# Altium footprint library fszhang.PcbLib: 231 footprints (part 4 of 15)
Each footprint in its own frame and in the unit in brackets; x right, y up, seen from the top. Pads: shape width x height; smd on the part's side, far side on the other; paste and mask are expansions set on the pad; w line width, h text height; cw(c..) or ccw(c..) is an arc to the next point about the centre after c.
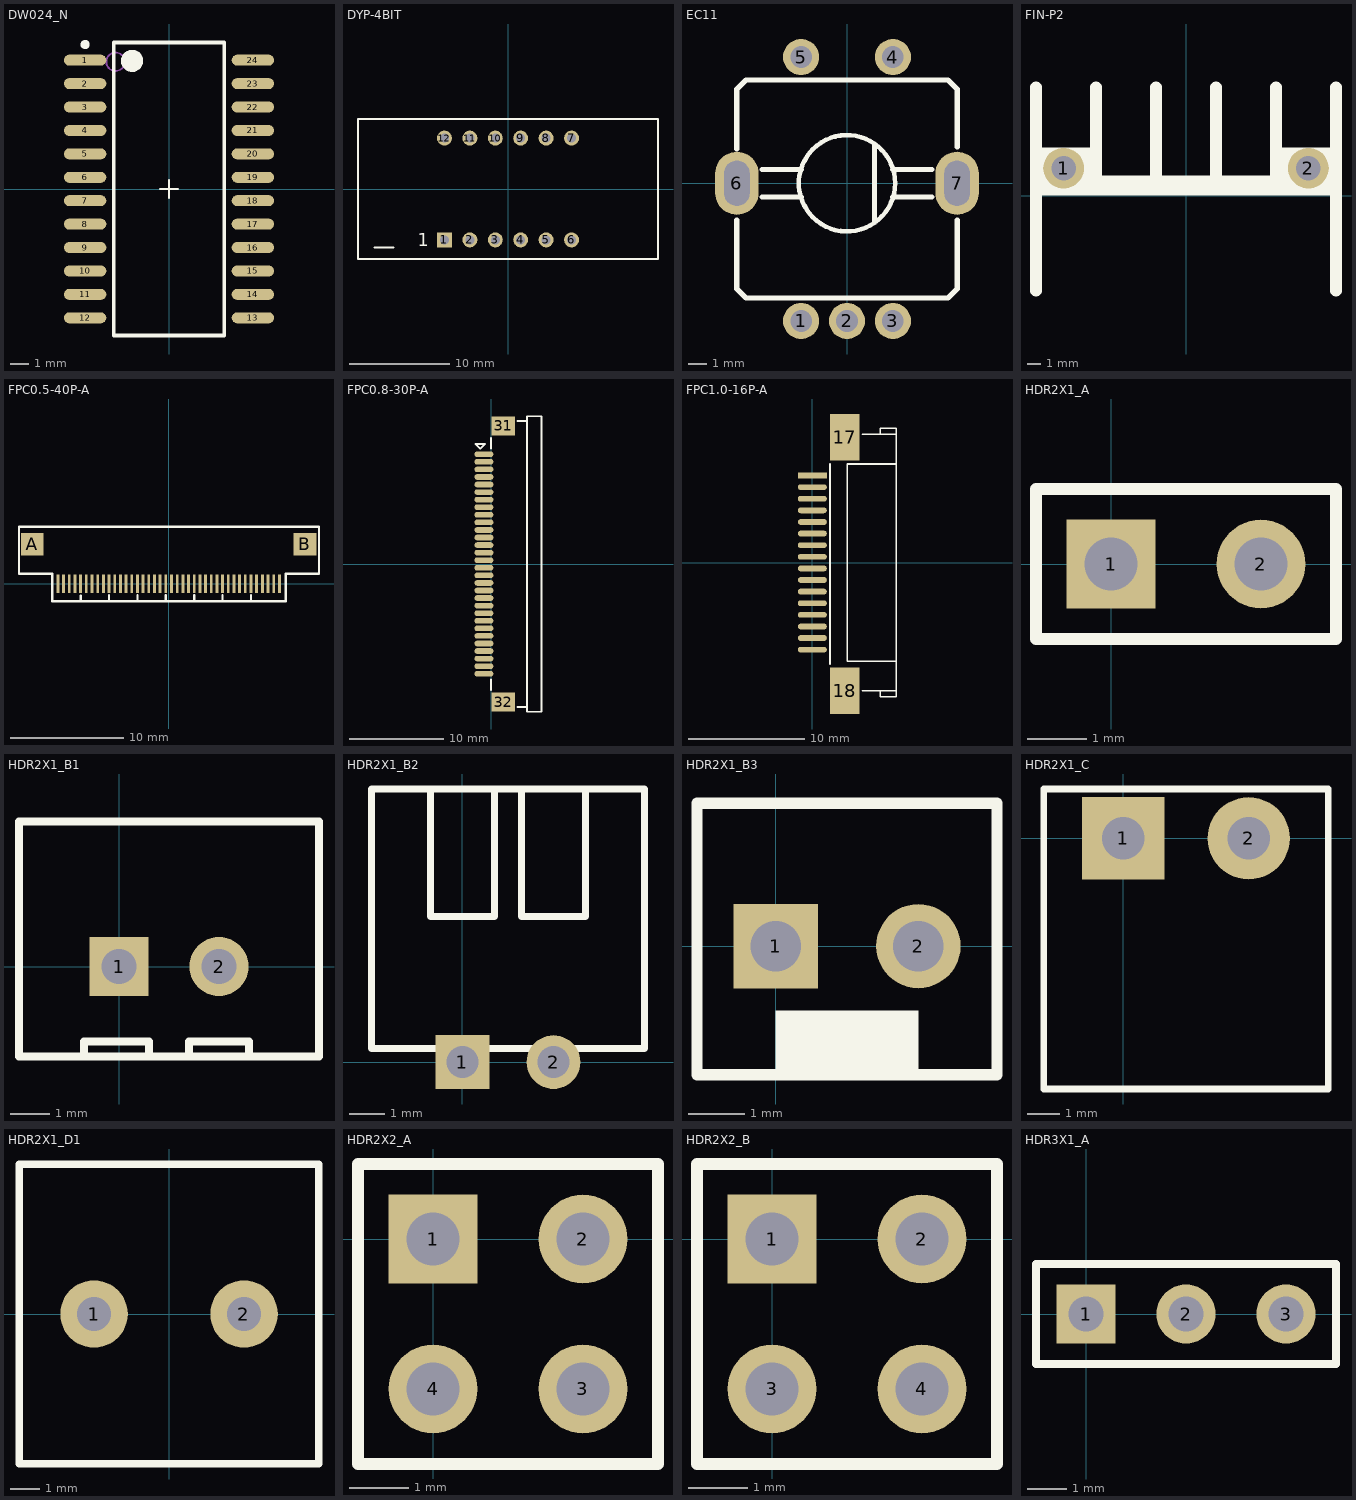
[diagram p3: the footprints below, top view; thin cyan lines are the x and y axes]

## DW024_N [mm] "74hc154"
height 2.65
pads (24):
  oval 2.3x0.6 smd: 1(-4.55,6.985) 2(-4.55,5.715) 3(-4.55,4.445) 4(-4.55,3.175) 5(-4.55,1.905) 6(-4.55,0.635) 7(-4.55,-0.635) 8(-4.55,-1.905) 9(-4.55,-3.175) 10(-4.55,-4.445) 11(-4.55,-5.715) 12(-4.55,-6.985) 13(4.55,-6.985) 14(4.55,-5.715) 15(4.55,-4.445) 16(4.55,-3.175) 17(4.55,-1.905) 18(4.55,-0.635) 19(4.55,0.635) 20(4.55,1.905) 21(4.55,3.175) 22(4.55,4.445) 23(4.55,5.715) 24(4.55,6.985)
Top Overlay:
  circle w0.25: c-4.55,7.835 r0.125
  circle w0.6: c-2,6.95 r0.3
  lines w0.1: -0.5,0 0.5,0 ; 0,-0.5 0,0.5
  lines w0.2: -3,-7.95 -3,7.95 3,7.95 3,-7.95 -3,-7.95
Mechanical 13:
  circle w0.1: c-2.9,6.9 r0.5
3D body: height 2.65, standoff 0, extent -3.8,-7.8 3.8,7.8

## DYP-4BIT [mm] "数码管"
height 1.2
pads (12):
  rect 1.5x1.5 hole 0.9: 1(-6.35,-5.08)
  round 1.5 hole 0.9: 2(-3.81,-5.08) 3(-1.27,-5.08) 4(1.27,-5.08) 5(3.81,-5.08) 6(6.35,-5.08) 7(6.35,5.08) 8(3.81,5.08) 9(1.27,5.08) 10(-1.27,5.08) 11(-3.81,5.08) 12(-6.35,5.08)
Top Overlay:
  lines w0.2: -13.335,-5.842 -11.43,-5.842 ; -14.986,-6.985 14.986,-6.985 14.986,6.985 -14.986,6.985 -14.986,-6.985
  text "1" at -9.017,-5.715 h1.27

## EC11 [mm]
pads (7):
  round 2 hole 1.2: 1(-2.54,-7.62) 2(0,-7.62) 3(2.54,-7.62) 4(2.54,6.985) 5(-2.54,6.985)
  oval 2.4x3.5 hole 1.4 slot 2.5 at 90 deg: 6(-6.096,0) 7(6.096,0)
Top Overlay:
  circle w0.254: c0,0 r2.667
  lines w0.3: -6.096,-2.032 -6.096,-5.842 -5.588,-6.35 5.588,-6.35 6.096,-5.842 6.096,-2.032 ; -6.096,1.905 -6.096,5.207 -5.588,5.715 5.588,5.715 6.096,5.207 6.096,2.032 ; -4.699,-0.762 -2.54,-0.762 ; -4.699,0.762 -2.54,0.762 ; 1.524,-2.159 1.524,2.159 ; 2.54,-0.762 4.699,-0.762 ; 2.54,0.762 4.699,0.762

## FIN-P2 [mm] "散热片"
height 1.9
pads (2):
  round 3 hole 1.8: 1(-9.017,2.032) 2(9.017,2.032)
Top Overlay:
  rectangle: 6.629,1.27 11.049,3.556
  rectangle: -11.049,0.889 -6.629,3.556
  lines w0.85: -11.049,-7 -11.049,8 ; -6.629,0.762 -6.629,8.001 ; -2.21,0.762 -2.21,8.001 ; 2.21,0.762 2.21,8.001 ; 6.629,0.762 6.629,8.001 ; 11.049,-7 11.049,8
  lines w1.5: -10.668,0.762 10.668,0.762

## FPC0.5-40P-A [mm]
height 1
pads (42):
  rect 0.25x1.6 smd: 1(-9.78,0.011) 2(-9.28,0.011) 3(-8.78,0.011) 4(-8.28,0.011) 5(-7.78,0.011) 6(-7.28,0.011) 7(-6.78,0.011) 8(-6.28,0.011) 9(-5.78,0.011) 10(-5.28,0.011) 11(-4.78,0.011) 12(-4.28,0.011) 13(-3.78,0.011) 14(-3.28,0.011) 15(-2.78,0.011) 16(-2.28,0.011) 17(-1.78,0.011) 18(-1.28,0.011) 19(-0.78,0.011) 20(-0.28,0.011) 21(0.22,0.011) 22(0.72,0.011) 23(1.22,0.011) 24(1.72,0.011) 25(2.22,0.011) 26(2.72,0.011) 27(3.22,0.011) 28(3.72,0.011) 29(4.22,0.011) 30(4.72,0.011) 31(5.22,0.011) 32(5.72,0.011) 33(6.22,0.011) 34(6.72,0.011) 35(7.22,0.011) 36(7.72,0.011) 37(8.22,0.011) 38(8.72,0.011) 39(9.22,0.011) 40(9.72,0.011)
  rect 2x2 smd: A(-12.029,3.5) B(11.971,3.5)
Top Overlay:
  lines w0.2: -10.287,-1.524 -10.287,0.889 -13.208,0.889 -13.208,5.036 13.208,5.036 13.208,1.27 13.208,0.889 10.287,0.889 10.287,-1.514 -10.287,-1.514 ; -7.78,-1.514 -7.78,-1.014 ; -5.28,-1.514 -5.28,-0.989 ; -2.78,-1.489 -2.78,-0.989 ; -0.28,-1.464 -0.28,-0.964 ; 2.22,-1.464 2.22,-0.964 ; 4.72,-1.464 4.72,-0.964 ; 7.22,-1.464 7.22,-0.964

## FPC0.8-30P-A [mm] "FPC"
height 1.2
pads (32):
  oval 2x0.6 smd: 1(-0.762,11.6) 2(-0.762,10.8) 3(-0.762,10) 4(-0.762,9.2) 5(-0.762,8.4) 6(-0.762,7.6) 7(-0.762,6.8) 8(-0.762,6) 9(-0.762,5.2) 10(-0.762,4.4) 11(-0.762,3.6) 12(-0.762,2.8) 13(-0.762,2) 14(-0.762,1.2) 15(-0.762,0.4) 16(-0.762,-0.4) 17(-0.762,-1.2) 18(-0.762,-2) 19(-0.762,-2.8) 20(-0.762,-3.6) 21(-0.762,-4.4) 22(-0.762,-5.2) 23(-0.762,-6) 24(-0.762,-6.8) 25(-0.762,-7.6) 26(-0.762,-8.4) 27(-0.762,-9.2) 28(-0.762,-10) 29(-0.762,-10.8) 30(-0.762,-11.6)
  rect 2.5x2 smd: 31(1.27,14.605) 32(1.27,-14.605)
Top Overlay:
  lines w0.2: 0,-13.335 0,-12.192 ; 0,12.192 0,13.335 ; 2.794,-15.113 3.81,-15.113 ; 2.794,15.113 3.81,15.113 ; 3.81,-15.113 3.81,-15.621 5.334,-15.621 5.334,15.621 3.81,15.621 3.81,15.113 ; 3.81,-15.113 3.81,15.113 ; -1.651,12.7 -1.524,12.7 -0.635,12.7 -1.143,12.192 -1.651,12.7

## FPC1.0-16P-A [mm] "FPC"
height 1.2
pads (18):
  rect 2.5x0.5 smd: 1(0,7.493)
  oval 2.5x0.5 smd: 2(0,6.493) 3(0,5.493) 4(0,4.493) 5(0,3.493) 6(0,2.493) 7(0,1.493) 8(0,0.493) 9(0,-0.507) 10(0,-1.507) 11(0,-2.507) 12(0,-3.507) 13(0,-4.507) 14(0,-5.507) 15(0,-6.507) 16(0,-7.507)
  rect 2.5x4 smd: 17(2.794,10.795) 18(2.794,-11.049)
Top Overlay:
  lines w0.15: 1.524,-8.763 1.524,8.509 ; 4.318,-11.049 7.224,-11.049 ; 4.318,11.049 7.224,11.049 ; 5.842,11.049 5.842,11.557 7.224,11.557 7.224,11.049 ; 6.096,-11.049 5.842,-11.049 5.842,-11.557 7.224,-11.557 7.224,-11.049 ; 7.224,-8.507 3,-8.507 3,8.493 7.224,8.493 ; 7.224,-11.049 7.224,11.049

## HDR2X1_A [mm] "Connector; Header; 2 Position"
height 7.01
pads (2):
  rect 1.5x1.5 hole 0.9: 1(0,0)
  round 1.5 hole 0.9: 2(2.54,0)
Top Overlay:
  lines w0.2: -1.27,-1.27 3.81,-1.27 3.81,1.27 -1.27,1.27 -1.27,-1.27

## HDR2X1_B1 [mm] "Connector; Header; 4 Position"
height 1.6
pads (2):
  rect 1.5x1.5 hole 0.9: 1(0,0)
  round 1.5 hole 0.9: 2(2.54,0)
Top Overlay:
  lines w0.2: -0.889,-2.286 -0.889,-1.905 0.762,-1.905 0.762,-2.286 ; 1.778,-2.286 1.778,-1.905 3.302,-1.905 3.302,-2.286 ; -2.54,-2.286 5.08,-2.286 5.08,3.683 -2.54,3.683 -2.54,-2.286
3D body: height 1.5, standoff 0, extent -2.413,-2.159 5.08,3.556

## HDR2X1_B2 [mm] "Connector; Header; 4 Position"
height 1.6
pads (2):
  rect 1.5x1.5 hole 0.9: 1(0,0)
  round 1.5 hole 0.9: 2(2.54,0)
Top Overlay:
  lines w0.2: -0.889,7.62 -0.889,4.064 0.889,4.064 0.889,7.62 ; 1.651,7.62 1.651,4.064 3.429,4.064 3.429,7.62 ; -2.54,0.381 5.08,0.381 5.08,7.62 -2.54,7.62 -2.54,0.381
3D body: height 1.5, standoff 0, extent -2.54,0.381 5.08,7.62

## HDR2X1_B3 [mm] "Connector; Header; 4 Position"
height 1.6
pads (2):
  rect 1.5x1.5 hole 0.9: 1(0,0)
  round 1.5 hole 0.9: 2(2.54,0)
Top Overlay:
  rectangle: 0,-2.286 2.54,-1.143
  lines w0.2: -1.397,-2.286 3.937,-2.286 3.937,2.54 -1.397,2.54 -1.397,-2.286
3D body: height 1.5, standoff 0, extent -1.397,-2.286 3.937,2.54

## HDR2X1_C [mm] "3.81接插件"
height 7
pads (2):
  rect 2.5x2.5 hole 1.3: 1(0,0)
  round 2.5 hole 1.3: 2(3.81,0)
Top Overlay:
  lines w0.2: -2.413,-7.62 -2.413,1.5 6.223,1.5 6.223,-7.62 -2.413,-7.62
3D body: height 5, standoff 0, extent -2.413,-7.62 6.223,1.397

## HDR2X1_D1 [mil] "5.08mm端子"
height 500
pads (2):
  round 90 hole 45: 1(-100,0) 2(100,0)
Top Overlay:
  lines w10: -200,-200 -200,200 200,200 200,-200 -200,-200

## HDR2X2_A [mm] "Connector; Header; 2 Position"
height 7.01
pads (4):
  rect 1.5x1.5 hole 0.9: 1(0,0)
  round 1.5 hole 0.9: 2(2.54,0) 3(2.54,-2.54) 4(0,-2.54)
Top Overlay:
  lines w0.2: -1.27,-3.81 -1.27,1.27 3.81,1.27 3.81,-3.81 -1.27,-3.81

## HDR2X2_B [mm] "Connector; Header; 2 Position"
height 7.01
pads (4):
  rect 1.5x1.5 hole 0.9: 1(0,0)
  round 1.5 hole 0.9: 2(2.54,0) 3(0,-2.54) 4(2.54,-2.54)
Top Overlay:
  lines w0.2: -1.27,-3.81 3.81,-3.81 3.81,1.27 -1.27,1.27 -1.27,-3.81

## HDR3X1_A [mm] "Connector; Header; 3 Position"
height 1.5
pads (3):
  rect 1.5x1.5 hole 0.9: 1(0,0)
  round 1.5 hole 0.9: 2(2.54,0) 3(5.08,0)
Top Overlay:
  lines w0.2: -1.27,-1.27 -1.27,1.27 6.35,1.27 6.35,-1.27 -1.27,-1.27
